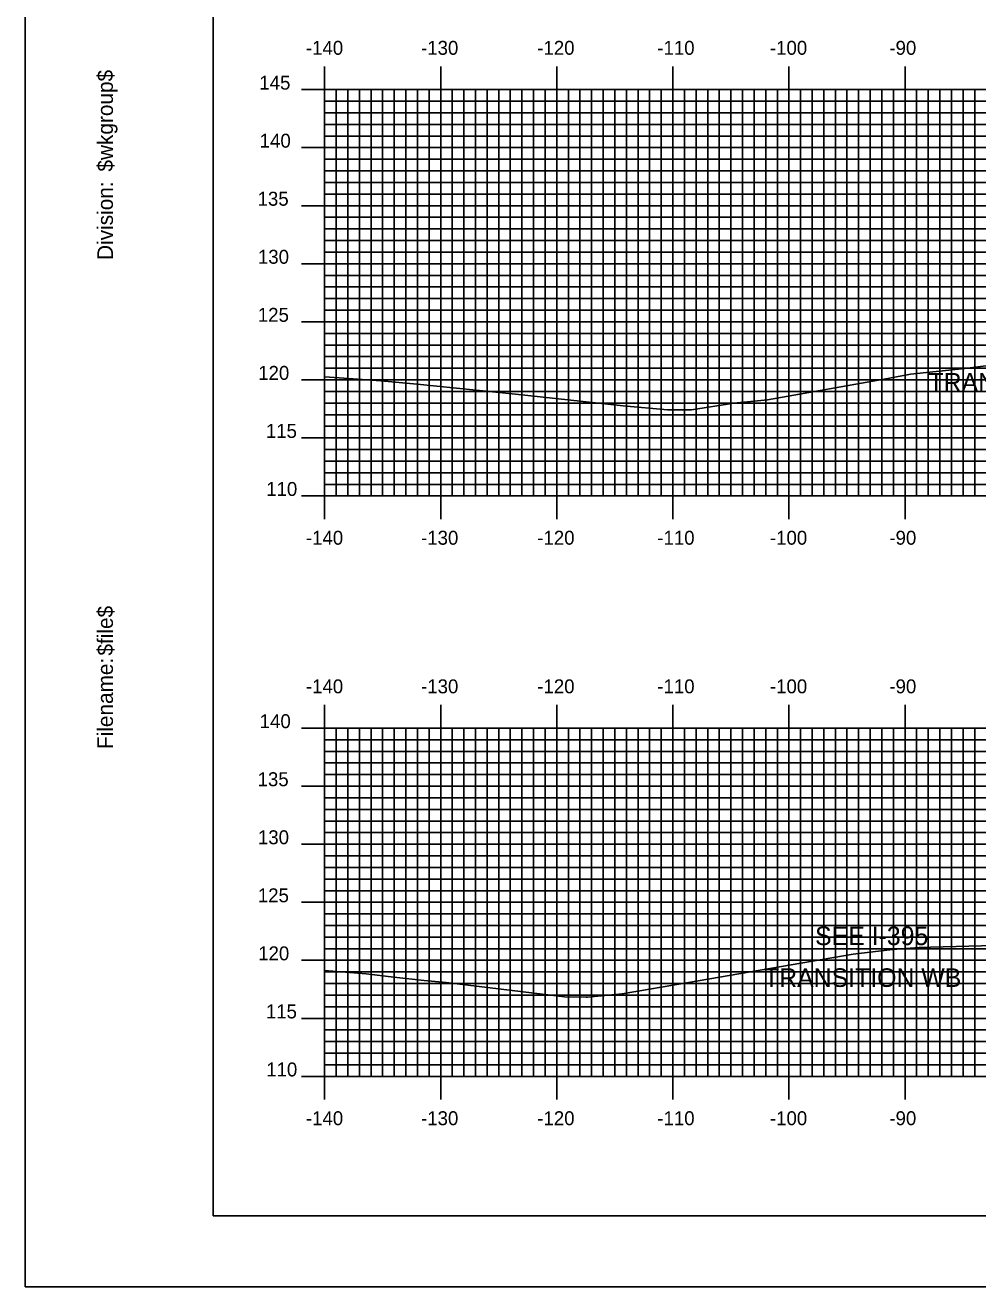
# Model space of a CAD drawing. Extents: x 852934 to 853277, y 364661 to 364881.
# Drawn here: x 852934 to 853016, y 364661.3 to 364769.9 of the extents above; entities that cross this region are included whole.
import ezdxf

# ---------------------------------------------------------------- set-up
doc = ezdxf.new("R2010")
doc.units = 0
for name, color, linetype in [('ANNOTATION', 7, 'Continuous'), ('BORDER', 7, 'Continuous'), ('H_V ANNOTATION', 7, 'Continuous'), ('MAJOR', 7, 'Continuous'), ('MINOR', 7, 'Continuous'), ('PLOT BOUNDARY', 7, 'Continuous'), ('S_Roadway_Centerline', 7, 'Continuous')]:
    doc.layers.add(name, color=color, linetype=linetype)

msp = doc.modelspace()

# ---------------------------------------------------------------- linework, layer by layer
at = {"layer": 'BORDER'}
msp.add_lwpolyline([(852950.18, 364667.37), (853270.18, 364667.37), (853270.18, 364877.37), (852950.18, 364877.37)], close=True, dxfattribs=at)
at = {"layer": 'MAJOR'}
for p, q in [((852959.78, 364766.37), (852959.78, 364764.37)), ((852969.78, 364766.37), (852969.78, 364764.37)), ((852979.78, 364766.37), (852979.78, 364764.37)), ((852989.78, 364766.37), (852989.78, 364764.37)), ((852999.78, 364766.37), (852999.78, 364764.37)), ((853009.78, 364766.37), (853009.78, 364764.37)), ((852957.78, 364764.37), (852959.78, 364764.37)), ((852959.78, 364764.37), (853239.78, 364764.37)), ((852959.78, 364729.37), (852959.78, 364764.37)), ((852959.78, 364729.37), (852959.78, 364764.37)), ((852959.78, 364764.37), (853239.78, 364764.37)), ((852969.78, 364729.37), (852969.78, 364764.37)), ((852979.78, 364729.37), (852979.78, 364764.37)), ((852989.78, 364729.37), (852989.78, 364764.37)), ((852999.78, 364729.37), (852999.78, 364764.37)), ((853009.78, 364729.37), (853009.78, 364764.37)), ((852957.78, 364759.37), (852959.78, 364759.37)), ((852959.78, 364759.37), (853239.78, 364759.37)), ((852957.78, 364754.37), (852959.78, 364754.37)), ((852959.78, 364754.37), (853239.78, 364754.37)), ((852957.78, 364749.37), (852959.78, 364749.37)), ((852959.78, 364749.37), (853239.78, 364749.37)), ((852957.78, 364744.37), (852959.78, 364744.37)), ((852959.78, 364744.37), (853239.78, 364744.37)), ((852957.78, 364739.37), (852959.78, 364739.37)), ((852959.78, 364739.37), (853239.78, 364739.37)), ((852957.78, 364734.37), (852959.78, 364734.37)), ((852959.78, 364734.37), (853239.78, 364734.37)), ((852957.78, 364729.37), (852959.78, 364729.37)), ((852959.78, 364729.37), (853239.78, 364729.37)), ((852959.78, 364729.37), (853239.78, 364729.37)), ((852959.78, 364727.37), (852959.78, 364729.37)), ((852969.78, 364727.37), (852969.78, 364729.37)), ((852979.78, 364727.37), (852979.78, 364729.37)), ((852989.78, 364727.37), (852989.78, 364729.37)), ((852999.78, 364727.37), (852999.78, 364729.37)), ((853009.78, 364727.37), (853009.78, 364729.37)), ((852959.78, 364711.37), (852959.78, 364709.37)), ((852969.78, 364711.37), (852969.78, 364709.37)), ((852979.78, 364711.37), (852979.78, 364709.37)), ((852989.78, 364711.37), (852989.78, 364709.37)), ((852999.78, 364711.37), (852999.78, 364709.37)), ((853009.78, 364711.37), (853009.78, 364709.37)), ((852957.78, 364709.37), (852959.78, 364709.37)), ((852959.78, 364709.37), (853239.78, 364709.37)), ((852959.78, 364679.37), (852959.78, 364709.37)), ((852959.78, 364679.37), (852959.78, 364709.37)), ((852959.78, 364709.37), (853239.78, 364709.37)), ((852969.78, 364679.37), (852969.78, 364709.37)), ((852979.78, 364679.37), (852979.78, 364709.37)), ((852989.78, 364679.37), (852989.78, 364709.37)), ((852999.78, 364679.37), (852999.78, 364709.37)), ((853009.78, 364679.37), (853009.78, 364709.37)), ((852957.78, 364704.37), (852959.78, 364704.37)), ((852959.78, 364704.37), (853239.78, 364704.37)), ((852957.78, 364699.37), (852959.78, 364699.37)), ((852959.78, 364699.37), (853239.78, 364699.37)), ((852957.78, 364694.37), (852959.78, 364694.37)), ((852959.78, 364694.37), (853239.78, 364694.37)), ((852957.78, 364689.37), (852959.78, 364689.37)), ((852959.78, 364689.37), (853239.78, 364689.37)), ((852957.78, 364684.37), (852959.78, 364684.37)), ((852959.78, 364684.37), (853239.78, 364684.37)), ((852957.78, 364679.37), (852959.78, 364679.37)), ((852959.78, 364679.37), (853239.78, 364679.37)), ((852959.78, 364679.37), (853239.78, 364679.37)), ((852959.78, 364677.37), (852959.78, 364679.37)), ((852969.78, 364677.37), (852969.78, 364679.37)), ((852979.78, 364677.37), (852979.78, 364679.37)), ((852989.78, 364677.37), (852989.78, 364679.37)), ((852999.78, 364677.37), (852999.78, 364679.37)), ((853009.78, 364677.37), (853009.78, 364679.37))]:
    msp.add_line(p, q, dxfattribs=at)
at = {"layer": 'MINOR'}
for p, q in [((852960.78, 364729.37), (852960.78, 364764.37)), ((852961.78, 364729.37), (852961.78, 364764.37)), ((852962.78, 364729.37), (852962.78, 364764.37)), ((852963.78, 364729.37), (852963.78, 364764.37)), ((852964.78, 364729.37), (852964.78, 364764.37)), ((852965.78, 364729.37), (852965.78, 364764.37)), ((852966.78, 364729.37), (852966.78, 364764.37)), ((852967.78, 364729.37), (852967.78, 364764.37)), ((852968.78, 364729.37), (852968.78, 364764.37)), ((852970.78, 364729.37), (852970.78, 364764.37)), ((852971.78, 364729.37), (852971.78, 364764.37)), ((852972.78, 364729.37), (852972.78, 364764.37)), ((852973.78, 364729.37), (852973.78, 364764.37)), ((852974.78, 364729.37), (852974.78, 364764.37)), ((852975.78, 364729.37), (852975.78, 364764.37)), ((852976.78, 364729.37), (852976.78, 364764.37)), ((852977.78, 364729.37), (852977.78, 364764.37)), ((852978.78, 364729.37), (852978.78, 364764.37)), ((852980.78, 364729.37), (852980.78, 364764.37)), ((852981.78, 364729.37), (852981.78, 364764.37)), ((852982.78, 364729.37), (852982.78, 364764.37)), ((852983.78, 364729.37), (852983.78, 364764.37)), ((852984.78, 364729.37), (852984.78, 364764.37)), ((852985.78, 364729.37), (852985.78, 364764.37)), ((852986.78, 364729.37), (852986.78, 364764.37)), ((852987.78, 364729.37), (852987.78, 364764.37)), ((852988.78, 364729.37), (852988.78, 364764.37)), ((852990.78, 364729.37), (852990.78, 364764.37)), ((852991.78, 364729.37), (852991.78, 364764.37)), ((852992.78, 364729.37), (852992.78, 364764.37)), ((852993.78, 364729.37), (852993.78, 364764.37)), ((852994.78, 364729.37), (852994.78, 364764.37)), ((852995.78, 364729.37), (852995.78, 364764.37)), ((852996.78, 364729.37), (852996.78, 364764.37)), ((852997.78, 364729.37), (852997.78, 364764.37)), ((852998.78, 364729.37), (852998.78, 364764.37)), ((853000.78, 364729.37), (853000.78, 364764.37)), ((853001.78, 364729.37), (853001.78, 364764.37)), ((853002.78, 364729.37), (853002.78, 364764.37)), ((853003.78, 364729.37), (853003.78, 364764.37)), ((853004.78, 364729.37), (853004.78, 364764.37)), ((853005.78, 364729.37), (853005.78, 364764.37)), ((853006.78, 364729.37), (853006.78, 364764.37)), ((853007.78, 364729.37), (853007.78, 364764.37)), ((853008.78, 364729.37), (853008.78, 364764.37)), ((853010.78, 364729.37), (853010.78, 364764.37)), ((853011.78, 364729.37), (853011.78, 364764.37)), ((853012.78, 364729.37), (853012.78, 364764.37)), ((853013.78, 364729.37), (853013.78, 364764.37)), ((853014.78, 364729.37), (853014.78, 364764.37)), ((853015.78, 364729.37), (853015.78, 364764.37)), ((852959.78, 364763.37), (853239.78, 364763.37)), ((852959.78, 364763.37), (852961.79, 364763.37)), ((852959.78, 364762.37), (853239.78, 364762.37)), ((852959.78, 364762.37), (852961.79, 364762.37)), ((852959.78, 364761.37), (853239.78, 364761.37)), ((852959.78, 364761.37), (852961.79, 364761.37)), ((852959.78, 364760.37), (853239.78, 364760.37)), ((852959.78, 364760.37), (852961.79, 364760.37)), ((852959.78, 364758.37), (853239.78, 364758.37)), ((852959.78, 364758.37), (852961.79, 364758.37)), ((852959.78, 364757.37), (853239.78, 364757.37)), ((852959.78, 364757.37), (852961.79, 364757.37)), ((852959.78, 364756.37), (853239.78, 364756.37)), ((852959.78, 364756.37), (852961.79, 364756.37)), ((852959.78, 364755.37), (853239.78, 364755.37)), ((852959.78, 364755.37), (852961.79, 364755.37)), ((852959.78, 364753.37), (853239.78, 364753.37)), ((852959.78, 364753.37), (852961.79, 364753.37)), ((852959.78, 364752.37), (853239.78, 364752.37)), ((852959.78, 364752.37), (852961.79, 364752.37)), ((852959.78, 364751.37), (853239.78, 364751.37)), ((852959.78, 364751.37), (852961.79, 364751.37)), ((852959.78, 364750.37), (853239.78, 364750.37)), ((852959.78, 364750.37), (852961.79, 364750.37)), ((852959.78, 364748.37), (853239.78, 364748.37)), ((852959.78, 364748.37), (852961.79, 364748.37)), ((852959.78, 364747.37), (853239.78, 364747.37)), ((852959.78, 364747.37), (852961.79, 364747.37)), ((852959.78, 364746.37), (853239.78, 364746.37)), ((852959.78, 364746.37), (852961.79, 364746.37)), ((852959.78, 364745.37), (853239.78, 364745.37)), ((852959.78, 364745.37), (852961.79, 364745.37)), ((852959.78, 364743.37), (853239.78, 364743.37)), ((852959.78, 364743.37), (852961.79, 364743.37)), ((852959.78, 364742.37), (853239.78, 364742.37)), ((852959.78, 364742.37), (852961.79, 364742.37)), ((852959.78, 364741.37), (853239.78, 364741.37)), ((852959.78, 364741.37), (852961.79, 364741.37)), ((852959.78, 364740.37), (853239.78, 364740.37)), ((852959.78, 364740.37), (852961.79, 364740.37)), ((852959.78, 364738.37), (853239.78, 364738.37)), ((852959.78, 364738.37), (852961.79, 364738.37)), ((852959.78, 364737.37), (853239.78, 364737.37)), ((852959.78, 364737.37), (852961.79, 364737.37)), ((852959.78, 364736.37), (853239.78, 364736.37)), ((852959.78, 364736.37), (852961.79, 364736.37)), ((852959.78, 364735.37), (853239.78, 364735.37)), ((852959.78, 364735.37), (852961.79, 364735.37)), ((852959.78, 364733.37), (853239.78, 364733.37)), ((852959.78, 364733.37), (852961.79, 364733.37)), ((852959.78, 364732.37), (853239.78, 364732.37)), ((852959.78, 364732.37), (852961.79, 364732.37)), ((852959.78, 364731.37), (853239.78, 364731.37)), ((852959.78, 364731.37), (852961.79, 364731.37)), ((852959.78, 364730.37), (853239.78, 364730.37)), ((852959.78, 364730.37), (852961.79, 364730.37)), ((852960.78, 364679.37), (852960.78, 364709.37)), ((852961.78, 364679.37), (852961.78, 364709.37)), ((852962.78, 364679.37), (852962.78, 364709.37)), ((852963.78, 364679.37), (852963.78, 364709.37)), ((852964.78, 364679.37), (852964.78, 364709.37)), ((852965.78, 364679.37), (852965.78, 364709.37)), ((852966.78, 364679.37), (852966.78, 364709.37)), ((852967.78, 364679.37), (852967.78, 364709.37)), ((852968.78, 364679.37), (852968.78, 364709.37)), ((852970.78, 364679.37), (852970.78, 364709.37)), ((852971.78, 364679.37), (852971.78, 364709.37)), ((852972.78, 364679.37), (852972.78, 364709.37)), ((852973.78, 364679.37), (852973.78, 364709.37)), ((852974.78, 364679.37), (852974.78, 364709.37)), ((852975.78, 364679.37), (852975.78, 364709.37)), ((852976.78, 364679.37), (852976.78, 364709.37)), ((852977.78, 364679.37), (852977.78, 364709.37)), ((852978.78, 364679.37), (852978.78, 364709.37)), ((852980.78, 364679.37), (852980.78, 364709.37)), ((852981.78, 364679.37), (852981.78, 364709.37)), ((852982.78, 364679.37), (852982.78, 364709.37)), ((852983.78, 364679.37), (852983.78, 364709.37)), ((852984.78, 364679.37), (852984.78, 364709.37)), ((852985.78, 364679.37), (852985.78, 364709.37)), ((852986.78, 364679.37), (852986.78, 364709.37)), ((852987.78, 364679.37), (852987.78, 364709.37)), ((852988.78, 364679.37), (852988.78, 364709.37)), ((852990.78, 364679.37), (852990.78, 364709.37)), ((852991.78, 364679.37), (852991.78, 364709.37)), ((852992.78, 364679.37), (852992.78, 364709.37)), ((852993.78, 364679.37), (852993.78, 364709.37)), ((852994.78, 364679.37), (852994.78, 364709.37)), ((852995.78, 364679.37), (852995.78, 364709.37)), ((852996.78, 364679.37), (852996.78, 364709.37)), ((852997.78, 364679.37), (852997.78, 364709.37)), ((852998.78, 364679.37), (852998.78, 364709.37)), ((853000.78, 364679.37), (853000.78, 364709.37)), ((853001.78, 364679.37), (853001.78, 364709.37)), ((853002.78, 364679.37), (853002.78, 364709.37)), ((853003.78, 364679.37), (853003.78, 364709.37)), ((853004.78, 364679.37), (853004.78, 364709.37)), ((853005.78, 364679.37), (853005.78, 364709.37)), ((853006.78, 364679.37), (853006.78, 364709.37)), ((853007.78, 364679.37), (853007.78, 364709.37)), ((853008.78, 364679.37), (853008.78, 364709.37)), ((853010.78, 364679.37), (853010.78, 364709.37)), ((853011.78, 364679.37), (853011.78, 364709.37)), ((853012.78, 364679.37), (853012.78, 364709.37)), ((853013.78, 364679.37), (853013.78, 364709.37)), ((853014.78, 364679.37), (853014.78, 364709.37)), ((853015.78, 364679.37), (853015.78, 364709.37)), ((852959.78, 364708.37), (853239.78, 364708.37)), ((852959.78, 364708.37), (852961.79, 364708.37)), ((852959.78, 364707.37), (853239.78, 364707.37)), ((852959.78, 364707.37), (852961.79, 364707.37)), ((852959.78, 364706.37), (853239.78, 364706.37)), ((852959.78, 364706.37), (852961.79, 364706.37)), ((852959.78, 364705.37), (853239.78, 364705.37)), ((852959.78, 364705.37), (852961.79, 364705.37)), ((852959.78, 364703.37), (853239.78, 364703.37)), ((852959.78, 364703.37), (852961.79, 364703.37)), ((852959.78, 364702.37), (853239.78, 364702.37)), ((852959.78, 364702.37), (852961.79, 364702.37)), ((852959.78, 364701.37), (853239.78, 364701.37)), ((852959.78, 364701.37), (852961.79, 364701.37)), ((852959.78, 364700.37), (853239.78, 364700.37)), ((852959.78, 364700.37), (852961.79, 364700.37)), ((852959.78, 364698.37), (853239.78, 364698.37)), ((852959.78, 364698.37), (852961.79, 364698.37)), ((852959.78, 364697.37), (853239.78, 364697.37)), ((852959.78, 364697.37), (852961.79, 364697.37)), ((852959.78, 364696.37), (853239.78, 364696.37)), ((852959.78, 364696.37), (852961.79, 364696.37)), ((852959.78, 364695.37), (853239.78, 364695.37)), ((852959.78, 364695.37), (852961.79, 364695.37)), ((852959.78, 364693.37), (853239.78, 364693.37)), ((852959.78, 364693.37), (852961.79, 364693.37)), ((852959.78, 364692.37), (853239.78, 364692.37)), ((852959.78, 364692.37), (852961.79, 364692.37)), ((852959.78, 364691.37), (853239.78, 364691.37)), ((852959.78, 364691.37), (852961.79, 364691.37)), ((852959.78, 364690.37), (853239.78, 364690.37)), ((852959.78, 364690.37), (852961.79, 364690.37)), ((852959.78, 364688.37), (853239.78, 364688.37)), ((852959.78, 364688.37), (852961.79, 364688.37)), ((852959.78, 364687.37), (853239.78, 364687.37)), ((852959.78, 364687.37), (852961.79, 364687.37)), ((852959.78, 364686.37), (853239.78, 364686.37)), ((852959.78, 364686.37), (852961.79, 364686.37)), ((852959.78, 364685.37), (853239.78, 364685.37)), ((852959.78, 364685.37), (852961.79, 364685.37)), ((852959.78, 364683.37), (853239.78, 364683.37)), ((852959.78, 364683.37), (852961.79, 364683.37)), ((852959.78, 364682.37), (853239.78, 364682.37)), ((852959.78, 364682.37), (852961.79, 364682.37)), ((852959.78, 364681.37), (853239.78, 364681.37)), ((852959.78, 364681.37), (852961.79, 364681.37)), ((852959.78, 364680.37), (853239.78, 364680.37)), ((852959.78, 364680.37), (852961.79, 364680.37))]:
    msp.add_line(p, q, dxfattribs=at)
at = {"layer": 'PLOT BOUNDARY'}
msp.add_lwpolyline([(852933.99, 364661.25), (853273.99, 364661.25), (853273.99, 364881.25), (852933.99, 364881.25)], close=True, dxfattribs=at)
at = {"layer": 'S_Roadway_Centerline'}
for points in [[(852959.78, 364739.63), (852961.05, 364739.53), (852964.63, 364739.3), (852967.75, 364738.99), (852976.22, 364738.15), (852985.51, 364737.13), (852989.32, 364736.78), (852991.39, 364736.79), (852995.02, 364737.36), (852997.93, 364737.64), (853008.29, 364739.48), (853010.24, 364739.85), (853014.93, 364740.36), (853017.85, 364740.71)], [(852959.78, 364688.49), (852963.35, 364688.2), (852965.74, 364687.93), (852968.35, 364687.62), (852970.25, 364687.46), (852980.45, 364686.23), (852982.32, 364686.21), (852982.44, 364686.2), (852985.42, 364686.49), (852991.14, 364687.45), (853005.32, 364689.9), (853008.71, 364690.31), (853010.99, 364690.47), (853011.98, 364690.51), (853018.57, 364690.67)]]:
    msp.add_lwpolyline(points, dxfattribs=at)

# ---------------------------------------------------------------- texts
at = {"layer": 'ANNOTATION'}
for s, p in [('TRANSITION WB', (853011.8, 364738.36)), ('SEE I-395 ', (853002.03, 364690.68)), ('TRANSITION WB', (852997.63, 364687.08))]:
    msp.add_text(s, height=1.6, dxfattribs=at).set_placement(p)
at = {"layer": 'BORDER'}
for s, p in [('$wkgroup$', (852941.55, 364757.31)), ('Division:', (852941.55, 364749.7)), ('$file$', (852941.55, 364715.62)), ('Filename:', (852941.55, 364707.57))]:
    msp.add_text(s, height=1.339, rotation=90, dxfattribs=at).set_placement(p)
at = {"layer": 'H_V ANNOTATION'}
for s, p in [('-140', (852958.17, 364767.37)), ('-130', (852968.09, 364767.37)), ('-120', (852978.1, 364767.37)), ('-110', (852988.44, 364767.37)), ('-100', (852998.14, 364767.37)), ('-90', (853008.43, 364767.37)), ('145', (852954.16, 364764.37)), ('140', (852954.19, 364759.37)), ('135', (852954.01, 364754.37)), ('130', (852954.04, 364749.37)), ('125', (852954.03, 364744.37)), ('120', (852954.06, 364739.37)), ('115', (852954.72, 364734.37)), ('110', (852954.75, 364729.37)), ('-140', (852958.17, 364725.17)), ('-130', (852968.09, 364725.17)), ('-120', (852978.1, 364725.17)), ('-110', (852988.44, 364725.17)), ('-100', (852998.14, 364725.17)), ('-90', (853008.43, 364725.17)), ('-140', (852958.17, 364712.37)), ('-130', (852968.09, 364712.37)), ('-120', (852978.1, 364712.37)), ('-110', (852988.44, 364712.37)), ('-100', (852998.14, 364712.37)), ('-90', (853008.43, 364712.37)), ('140', (852954.19, 364709.37)), ('135', (852954.01, 364704.37)), ('130', (852954.04, 364699.37)), ('125', (852954.03, 364694.37)), ('120', (852954.06, 364689.37)), ('115', (852954.72, 364684.37)), ('110', (852954.75, 364679.37)), ('-140', (852958.17, 364675.17)), ('-130', (852968.09, 364675.17)), ('-120', (852978.1, 364675.17)), ('-110', (852988.44, 364675.17)), ('-100', (852998.14, 364675.17)), ('-90', (853008.43, 364675.17))]:
    msp.add_text(s, height=1.2, dxfattribs=at).set_placement(p)
at = {"layer": 'MAJOR'}
for p in [(852959.77, 364729.37), (852959.77, 364679.37)]:
    msp.add_text('-', height=0.012, dxfattribs=at).set_placement(p)

doc.saveas('drawing.dxf')
